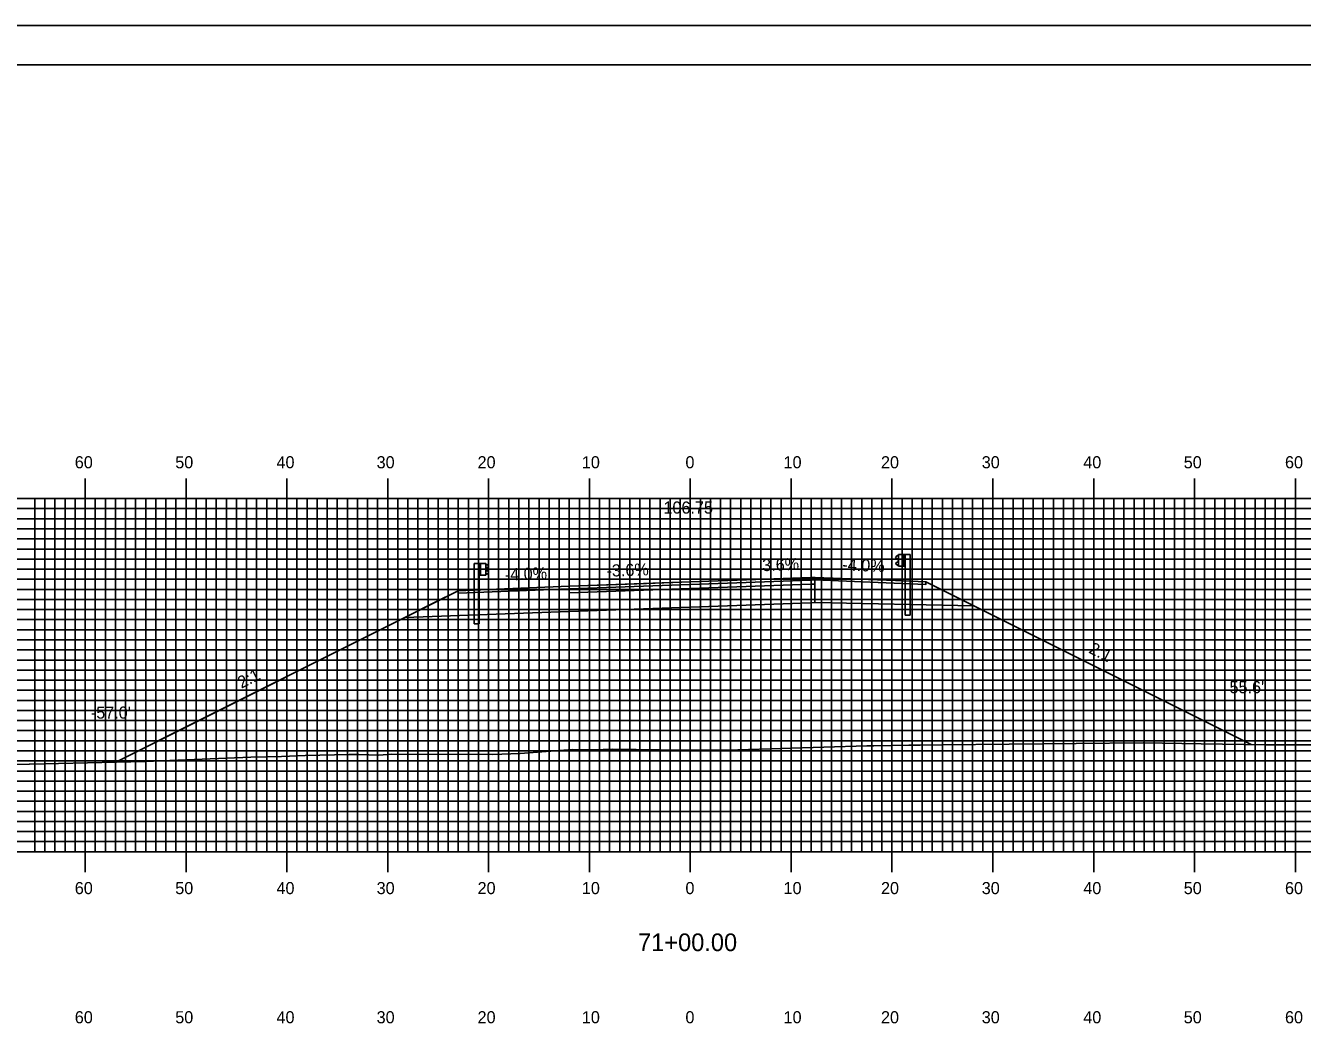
# Model space of a CAD drawing. Extents: x 1760217 to 1760560, y 442591 to 442811.
# Drawn here: x 1760316.8 to 1760443.4, y 442711.2 to 442810.5 of the extents above; entities that cross this region are included whole.
import ezdxf

# ---------------------------------------------------------------- set-up
doc = ezdxf.new("R2010")
doc.units = 0
for name, color, linetype in [('ANNOTATION', 7, 'Continuous'), ('BORDER', 7, 'Continuous'), ('D_Guardrail_Beam_Lt', 7, 'Continuous'), ('D_Guardrail_Beam_Rt', 7, 'Continuous'), ('D_Roadway_Centerline', 7, 'Continuous'), ('D_Roadway_Centerline_Text', 7, 'Continuous'), ('D_Roadway_Edge_Shoulder', 7, 'Continuous'), ('D_Roadway_Edge_TW', 7, 'Continuous'), ('D_Roadway_Pavement', 7, 'Continuous'), ('D_Roadway_SlopeLines', 7, 'Continuous'), ('D_Roadway_SubGrade', 7, 'Continuous'), ('D_Text_Standard', 7, 'Continuous'), ('H_V ANNOTATION', 7, 'Continuous'), ('MAJOR', 7, 'Continuous'), ('MINOR', 7, 'Continuous'), ('PLOT BOUNDARY', 7, 'Continuous'), ('S_Roadway_Centerline', 7, 'Continuous')]:
    doc.layers.add(name, color=color, linetype=linetype)

msp = doc.modelspace()

# ---------------------------------------------------------------- linework, layer by layer
at = {"layer": 'BORDER'}
msp.add_lwpolyline([(1760233.1, 442596.67), (1760553.1, 442596.67), (1760553.1, 442806.67), (1760233.1, 442806.67)], close=True, dxfattribs=at)
at = {"layer": 'D_Guardrail_Beam_Lt'}
for p, q in [((1760361.27, 442757.25), (1760361.27, 442751.25)), ((1760361.74, 442757.25), (1760361.27, 442757.25)), ((1760362.43, 442757.25), (1760361.74, 442757.25)), ((1760361.74, 442757.25), (1760361.74, 442756.08)), ((1760361.8, 442757.25), (1760361.8, 442756.08)), ((1760361.91, 442757.25), (1760361.91, 442756.08)), ((1760362.43, 442756.08), (1760362.43, 442757.25)), ((1760362.43, 442757.16), (1760362.5, 442757.15)), ((1760362.43, 442756.7), (1760362.43, 442756.63)), ((1760362.5, 442756.18), (1760362.43, 442756.16)), ((1760362.66, 442756.9), (1760362.47, 442756.76)), ((1760362.47, 442756.56), (1760362.66, 442756.43)), ((1760362.52, 442757.14), (1760362.66, 442757.04)), ((1760362.66, 442756.28), (1760362.52, 442756.18)), ((1760361.74, 442756.08), (1760362.43, 442756.08)), ((1760361.76, 442751.25), (1760361.76, 442756.08)), ((1760361.76, 442751.25), (1760361.27, 442751.25))]:
    msp.add_line(p, q, dxfattribs=at)
for centre, major_axis, start_param, end_param in [((1760362.51, 442756.7), (-0.0789, 0), 5.323254, 6.283185), ((1760362.51, 442756.63), (-0.0789, 0), 6.283185, 7.243116), ((1760362.5, 442757.11), (0.0417, 0), 0.959931, 1.376053), ((1760362.5, 442756.22), (0.0417, 0), 4.907132, 5.323254), ((1760362.61, 442756.97), (0.0877, 0), 5.323254, 7.243116), ((1760362.61, 442756.36), (0.0877, 0), 5.323254, 7.243116)]:
    msp.add_ellipse(centre, major_axis=major_axis, ratio=0.995501, start_param=start_param, end_param=end_param, dxfattribs=at)
at = {"layer": 'D_Guardrail_Beam_Rt'}
for p, q in [((1760403.25, 442758.02), (1760403.1, 442757.92)), ((1760403.1, 442757.77), (1760403.3, 442757.64)), ((1760403.3, 442757.44), (1760403.1, 442757.3)), ((1760403.34, 442758.04), (1760403.26, 442758.02)), ((1760403.33, 442757.57), (1760403.33, 442757.5)), ((1760403.34, 442758.12), (1760404.02, 442758.12)), ((1760403.34, 442756.96), (1760403.34, 442758.12)), ((1760403.86, 442758.12), (1760403.86, 442756.96)), ((1760403.96, 442758.12), (1760403.96, 442756.96)), ((1760404.02, 442758.12), (1760404.49, 442758.12)), ((1760404.02, 442758.12), (1760404.02, 442756.96)), ((1760404.49, 442758.12), (1760404.49, 442752.12)), ((1760403.1, 442757.16), (1760403.25, 442757.06)), ((1760403.26, 442757.05), (1760403.34, 442757.04)), ((1760404.02, 442756.96), (1760403.34, 442756.96)), ((1760404, 442752.12), (1760404, 442756.96)), ((1760404, 442752.12), (1760404.49, 442752.12))]:
    msp.add_line(p, q, dxfattribs=at)
for centre, major_axis, start_param, end_param in [((1760403.15, 442757.85), (-0.0877, 0), 5.323254, 7.243116), ((1760403.27, 442757.98), (-0.0417, 0), 4.907132, 5.323254), ((1760403.25, 442757.57), (0.0789, 0), 0, 0.959931), ((1760403.25, 442757.5), (0.0789, 0), 5.323254, 6.283185), ((1760403.15, 442757.23), (-0.0877, 0), 5.323254, 7.243116), ((1760403.27, 442757.09), (-0.0417, 0), 0.959931, 1.376053)]:
    msp.add_ellipse(centre, major_axis=major_axis, ratio=0.995501, start_param=start_param, end_param=end_param, dxfattribs=at)
at = {"layer": 'D_Roadway_Centerline'}
msp.add_lwpolyline([(1760325.68, 442737.53), (1760333.64, 442741.51), (1760354.41, 442751.9), (1760354.41, 442751.9), (1760357.2, 442753.29), (1760359.7, 442754.54), (1760361.82, 442754.63), (1760362.7, 442754.66), (1760362.7, 442754.66), (1760370.7, 442754.98), (1760370.71, 442754.98), (1760378.37, 442755.26), (1760382.7, 442755.41), (1760389.19, 442755.65), (1760394.7, 442755.85), (1760394.97, 442755.86), (1760395.06, 442755.86), (1760396.87, 442755.79), (1760403.06, 442755.54), (1760403.06, 442755.54), (1760406.07, 442755.42), (1760410.81, 442753.04), (1760438.32, 442739.29), (1760438.33, 442739.29)], dxfattribs=at)
at = {"layer": 'D_Roadway_Edge_Shoulder'}
for points in [[(1760370.7, 442754.98), (1760362.7, 442754.66), (1760362.7, 442754.66), (1760359.7, 442754.54), (1760359.7, 442754.29), (1760370.7, 442754.73)], [(1760395.06, 442755.86), (1760403.06, 442755.54), (1760403.06, 442755.54), (1760406.07, 442755.42), (1760406.07, 442755.17), (1760395.06, 442755.61)]]:
    msp.add_lwpolyline(points, close=True, dxfattribs=at)
at = {"layer": 'D_Roadway_Edge_TW'}
for points in [[(1760370.7, 442754.73), (1760370.7, 442754.98), (1760382.7, 442755.41), (1760394.7, 442755.85), (1760394.7, 442755.6), (1760382.7, 442755.16)], [(1760394.7, 442755.85), (1760395.06, 442755.86), (1760395.06, 442755.61), (1760394.7, 442755.6)]]:
    msp.add_lwpolyline(points, close=True, dxfattribs=at)
at = {"layer": 'D_Roadway_Pavement'}
for points in [[(1760370.7, 442754.32), (1760370.7, 442754.73), (1760382.7, 442755.16), (1760394.7, 442755.6), (1760394.7, 442755.18), (1760382.7, 442754.75)], [(1760394.7, 442755.6), (1760395.06, 442755.61), (1760395.06, 442755.19), (1760394.7, 442755.18)]]:
    msp.add_lwpolyline(points, close=True, dxfattribs=at)
for points in [[(1760395.06, 442755.61), (1760395.06, 442755.19)], [(1760395.06, 442755.61), (1760395.06, 442755.19)], [(1760370.7, 442754.73), (1760370.7, 442754.32)]]:
    msp.add_lwpolyline(points, dxfattribs=at)
at = {"layer": 'D_Roadway_SlopeLines'}
for points in [[(1760406.07, 442755.42), (1760438.33, 442739.29)], [(1760359.7, 442754.54), (1760325.68, 442737.53)]]:
    msp.add_lwpolyline(points, dxfattribs=at)
at = {"layer": 'D_Roadway_SubGrade'}
for points in [[(1760370.7, 442752.48), (1760370.7, 442754.32), (1760382.7, 442754.75), (1760394.7, 442755.18), (1760394.7, 442753.35), (1760382.7, 442752.91)], [(1760394.7, 442755.18), (1760395.06, 442755.19), (1760395.06, 442753.36), (1760394.7, 442753.35)], [(1760395.06, 442755.19), (1760395.06, 442755.61), (1760406.07, 442755.17), (1760406.07, 442755.42), (1760410.81, 442753.04), (1760395.06, 442753.36)], [(1760370.7, 442754.32), (1760370.7, 442754.73), (1760359.7, 442754.29), (1760359.7, 442754.54), (1760354.41, 442751.9), (1760370.7, 442752.48)]]:
    msp.add_lwpolyline(points, close=True, dxfattribs=at)
at = {"layer": 'MAJOR'}
for p, q in [((1760322.7, 442765.67), (1760322.7, 442763.67)), ((1760332.7, 442765.67), (1760332.7, 442763.67)), ((1760342.7, 442765.67), (1760342.7, 442763.67)), ((1760352.7, 442765.67), (1760352.7, 442763.67)), ((1760362.7, 442765.67), (1760362.7, 442763.67)), ((1760372.7, 442765.67), (1760372.7, 442763.67)), ((1760382.7, 442765.67), (1760382.7, 442763.67)), ((1760392.7, 442765.67), (1760392.7, 442763.67)), ((1760402.7, 442765.67), (1760402.7, 442763.67)), ((1760412.7, 442765.67), (1760412.7, 442763.67)), ((1760422.7, 442765.67), (1760422.7, 442763.67)), ((1760432.7, 442765.67), (1760432.7, 442763.67)), ((1760442.7, 442765.67), (1760442.7, 442763.67)), ((1760242.7, 442763.67), (1760522.7, 442763.67)), ((1760242.7, 442763.67), (1760522.7, 442763.67)), ((1760322.7, 442728.67), (1760322.7, 442763.67)), ((1760332.7, 442728.67), (1760332.7, 442763.67)), ((1760342.7, 442728.67), (1760342.7, 442763.67)), ((1760352.7, 442728.67), (1760352.7, 442763.67)), ((1760362.7, 442728.67), (1760362.7, 442763.67)), ((1760372.7, 442728.67), (1760372.7, 442763.67)), ((1760382.7, 442728.67), (1760382.7, 442763.67)), ((1760392.7, 442728.67), (1760392.7, 442763.67)), ((1760402.7, 442728.67), (1760402.7, 442763.67)), ((1760412.7, 442728.67), (1760412.7, 442763.67)), ((1760422.7, 442728.67), (1760422.7, 442763.67)), ((1760432.7, 442728.67), (1760432.7, 442763.67)), ((1760442.7, 442728.67), (1760442.7, 442763.67)), ((1760242.7, 442758.67), (1760522.7, 442758.67)), ((1760242.7, 442753.67), (1760522.7, 442753.67)), ((1760242.7, 442748.67), (1760522.7, 442748.67)), ((1760242.7, 442743.67), (1760522.7, 442743.67)), ((1760242.7, 442738.67), (1760522.7, 442738.67)), ((1760242.7, 442733.67), (1760522.7, 442733.67)), ((1760242.7, 442728.67), (1760522.7, 442728.67)), ((1760242.7, 442728.67), (1760522.7, 442728.67)), ((1760322.7, 442726.66), (1760322.7, 442728.67)), ((1760332.7, 442726.66), (1760332.7, 442728.67)), ((1760342.7, 442726.66), (1760342.7, 442728.67)), ((1760352.7, 442726.66), (1760352.7, 442728.67)), ((1760362.7, 442726.66), (1760362.7, 442728.67)), ((1760372.7, 442726.66), (1760372.7, 442728.67)), ((1760382.7, 442726.66), (1760382.7, 442728.67)), ((1760392.7, 442726.66), (1760392.7, 442728.67)), ((1760402.7, 442726.66), (1760402.7, 442728.67)), ((1760412.7, 442726.66), (1760412.7, 442728.67)), ((1760422.7, 442726.66), (1760422.7, 442728.67)), ((1760432.7, 442726.66), (1760432.7, 442728.67)), ((1760442.7, 442726.66), (1760442.7, 442728.67))]:
    msp.add_line(p, q, dxfattribs=at)
at = {"layer": 'MINOR'}
for p, q in [((1760242.7, 442762.67), (1760522.7, 442762.67)), ((1760317.7, 442728.67), (1760317.7, 442763.67)), ((1760318.7, 442728.67), (1760318.7, 442763.67)), ((1760319.7, 442728.67), (1760319.7, 442763.67)), ((1760320.7, 442728.67), (1760320.7, 442763.67)), ((1760321.7, 442728.67), (1760321.7, 442763.67)), ((1760323.7, 442728.67), (1760323.7, 442763.67)), ((1760324.7, 442728.67), (1760324.7, 442763.67)), ((1760325.7, 442728.67), (1760325.7, 442763.67)), ((1760326.7, 442728.67), (1760326.7, 442763.67)), ((1760327.7, 442728.67), (1760327.7, 442763.67)), ((1760328.7, 442728.67), (1760328.7, 442763.67)), ((1760329.7, 442728.67), (1760329.7, 442763.67)), ((1760330.7, 442728.67), (1760330.7, 442763.67)), ((1760331.7, 442728.67), (1760331.7, 442763.67)), ((1760333.7, 442728.67), (1760333.7, 442763.67)), ((1760334.7, 442728.67), (1760334.7, 442763.67)), ((1760335.7, 442728.67), (1760335.7, 442763.67)), ((1760336.7, 442728.67), (1760336.7, 442763.67)), ((1760337.7, 442728.67), (1760337.7, 442763.67)), ((1760338.7, 442728.67), (1760338.7, 442763.67)), ((1760339.7, 442728.67), (1760339.7, 442763.67)), ((1760340.7, 442728.67), (1760340.7, 442763.67)), ((1760341.7, 442728.67), (1760341.7, 442763.67)), ((1760343.7, 442728.67), (1760343.7, 442763.67)), ((1760344.7, 442728.67), (1760344.7, 442763.67)), ((1760345.7, 442728.67), (1760345.7, 442763.67)), ((1760346.7, 442728.67), (1760346.7, 442763.67)), ((1760347.7, 442728.67), (1760347.7, 442763.67)), ((1760348.7, 442728.67), (1760348.7, 442763.67)), ((1760349.7, 442728.67), (1760349.7, 442763.67)), ((1760350.7, 442728.67), (1760350.7, 442763.67)), ((1760351.7, 442728.67), (1760351.7, 442763.67)), ((1760353.7, 442728.67), (1760353.7, 442763.67)), ((1760354.7, 442728.67), (1760354.7, 442763.67)), ((1760355.7, 442728.67), (1760355.7, 442763.67)), ((1760356.7, 442728.67), (1760356.7, 442763.67)), ((1760357.7, 442728.67), (1760357.7, 442763.67)), ((1760358.7, 442728.67), (1760358.7, 442763.67)), ((1760359.7, 442728.67), (1760359.7, 442763.67)), ((1760360.7, 442728.67), (1760360.7, 442763.67)), ((1760361.7, 442728.67), (1760361.7, 442763.67)), ((1760363.7, 442728.67), (1760363.7, 442763.67)), ((1760364.7, 442728.67), (1760364.7, 442763.67)), ((1760365.7, 442728.67), (1760365.7, 442763.67)), ((1760366.7, 442728.67), (1760366.7, 442763.67)), ((1760367.7, 442728.67), (1760367.7, 442763.67)), ((1760368.7, 442728.67), (1760368.7, 442763.67)), ((1760369.7, 442728.67), (1760369.7, 442763.67)), ((1760370.7, 442728.67), (1760370.7, 442763.67)), ((1760371.7, 442728.67), (1760371.7, 442763.67)), ((1760373.7, 442728.67), (1760373.7, 442763.67)), ((1760374.7, 442728.67), (1760374.7, 442763.67)), ((1760375.7, 442728.67), (1760375.7, 442763.67)), ((1760376.7, 442728.67), (1760376.7, 442763.67)), ((1760377.7, 442728.67), (1760377.7, 442763.67)), ((1760378.7, 442728.67), (1760378.7, 442763.67)), ((1760379.7, 442728.67), (1760379.7, 442763.67)), ((1760380.7, 442728.67), (1760380.7, 442763.67)), ((1760381.7, 442728.67), (1760381.7, 442763.67)), ((1760383.7, 442728.67), (1760383.7, 442763.67)), ((1760384.7, 442728.67), (1760384.7, 442763.67)), ((1760385.7, 442728.67), (1760385.7, 442763.67)), ((1760386.7, 442728.67), (1760386.7, 442763.67)), ((1760387.7, 442728.67), (1760387.7, 442763.67)), ((1760388.7, 442728.67), (1760388.7, 442763.67)), ((1760389.7, 442728.67), (1760389.7, 442763.67)), ((1760390.7, 442728.67), (1760390.7, 442763.67)), ((1760391.7, 442728.67), (1760391.7, 442763.67)), ((1760393.7, 442728.67), (1760393.7, 442763.67)), ((1760394.7, 442728.67), (1760394.7, 442763.67)), ((1760395.7, 442728.67), (1760395.7, 442763.67)), ((1760396.7, 442728.67), (1760396.7, 442763.67)), ((1760397.7, 442728.67), (1760397.7, 442763.67)), ((1760398.7, 442728.67), (1760398.7, 442763.67)), ((1760399.7, 442728.67), (1760399.7, 442763.67)), ((1760400.7, 442728.67), (1760400.7, 442763.67)), ((1760401.7, 442728.67), (1760401.7, 442763.67)), ((1760403.7, 442728.67), (1760403.7, 442763.67)), ((1760404.7, 442728.67), (1760404.7, 442763.67)), ((1760405.7, 442728.67), (1760405.7, 442763.67)), ((1760406.7, 442728.67), (1760406.7, 442763.67)), ((1760407.7, 442728.67), (1760407.7, 442763.67)), ((1760408.7, 442728.67), (1760408.7, 442763.67)), ((1760409.7, 442728.67), (1760409.7, 442763.67)), ((1760410.7, 442728.67), (1760410.7, 442763.67)), ((1760411.7, 442728.67), (1760411.7, 442763.67)), ((1760413.7, 442728.67), (1760413.7, 442763.67)), ((1760414.7, 442728.67), (1760414.7, 442763.67)), ((1760415.7, 442728.67), (1760415.7, 442763.67)), ((1760416.7, 442728.67), (1760416.7, 442763.67)), ((1760417.7, 442728.67), (1760417.7, 442763.67)), ((1760418.7, 442728.67), (1760418.7, 442763.67)), ((1760419.7, 442728.67), (1760419.7, 442763.67)), ((1760420.7, 442728.67), (1760420.7, 442763.67)), ((1760421.7, 442728.67), (1760421.7, 442763.67)), ((1760423.7, 442728.67), (1760423.7, 442763.67)), ((1760424.7, 442728.67), (1760424.7, 442763.67)), ((1760425.7, 442728.67), (1760425.7, 442763.67)), ((1760426.7, 442728.67), (1760426.7, 442763.67)), ((1760427.7, 442728.67), (1760427.7, 442763.67)), ((1760428.7, 442728.67), (1760428.7, 442763.67)), ((1760429.7, 442728.67), (1760429.7, 442763.67)), ((1760430.7, 442728.67), (1760430.7, 442763.67)), ((1760431.7, 442728.67), (1760431.7, 442763.67)), ((1760433.7, 442728.67), (1760433.7, 442763.67)), ((1760434.7, 442728.67), (1760434.7, 442763.67)), ((1760435.7, 442728.67), (1760435.7, 442763.67)), ((1760436.7, 442728.67), (1760436.7, 442763.67)), ((1760437.7, 442728.67), (1760437.7, 442763.67)), ((1760438.7, 442728.67), (1760438.7, 442763.67)), ((1760439.7, 442728.67), (1760439.7, 442763.67)), ((1760440.7, 442728.67), (1760440.7, 442763.67)), ((1760441.7, 442728.67), (1760441.7, 442763.67)), ((1760242.7, 442761.67), (1760522.7, 442761.67)), ((1760242.7, 442760.67), (1760522.7, 442760.67)), ((1760242.7, 442759.67), (1760522.7, 442759.67)), ((1760242.7, 442757.67), (1760522.7, 442757.67)), ((1760242.7, 442756.67), (1760522.7, 442756.67)), ((1760242.7, 442755.67), (1760522.7, 442755.67)), ((1760242.7, 442754.67), (1760522.7, 442754.67)), ((1760242.7, 442752.67), (1760522.7, 442752.67)), ((1760242.7, 442751.67), (1760522.7, 442751.67)), ((1760242.7, 442750.67), (1760522.7, 442750.67)), ((1760242.7, 442749.67), (1760522.7, 442749.67)), ((1760242.7, 442747.67), (1760522.7, 442747.67)), ((1760242.7, 442746.67), (1760522.7, 442746.67)), ((1760242.7, 442745.67), (1760522.7, 442745.67)), ((1760242.7, 442744.67), (1760522.7, 442744.67)), ((1760242.7, 442742.67), (1760522.7, 442742.67)), ((1760242.7, 442741.67), (1760522.7, 442741.67)), ((1760242.7, 442740.67), (1760522.7, 442740.67)), ((1760242.7, 442739.67), (1760522.7, 442739.67)), ((1760242.7, 442737.67), (1760522.7, 442737.67)), ((1760242.7, 442736.67), (1760522.7, 442736.67)), ((1760242.7, 442735.67), (1760522.7, 442735.67)), ((1760242.7, 442734.67), (1760522.7, 442734.67)), ((1760242.7, 442732.67), (1760522.7, 442732.67)), ((1760242.7, 442731.67), (1760522.7, 442731.67)), ((1760242.7, 442730.67), (1760522.7, 442730.67)), ((1760242.7, 442729.67), (1760522.7, 442729.67))]:
    msp.add_line(p, q, dxfattribs=at)
at = {"layer": 'PLOT BOUNDARY'}
msp.add_lwpolyline([(1760216.91, 442590.55), (1760556.91, 442590.55), (1760556.91, 442810.55), (1760216.91, 442810.55)], close=True, dxfattribs=at)
at = {"layer": 'S_Roadway_Centerline'}
msp.add_lwpolyline([(1760305.63, 442737.28), (1760317.14, 442737.34), (1760317.18, 442737.34), (1760328.69, 442737.6), (1760339.12, 442738.03), (1760342.16, 442738.12), (1760344.52, 442738.2), (1760348.89, 442738.31), (1760349.83, 442738.32), (1760351.82, 442738.23), (1760353.1, 442738.33), (1760363.09, 442738.32), (1760365.83, 442738.4), (1760371.03, 442738.79), (1760373.09, 442738.78), (1760375.03, 442738.83), (1760379.68, 442738.77), (1760384.26, 442738.73), (1760387.42, 442738.76), (1760400.19, 442739.16), (1760400.45, 442739.17), (1760400.52, 442739.17), (1760400.9, 442739.18), (1760404.36, 442739.24), (1760405.48, 442739.22), (1760407.67, 442739.27), (1760427.62, 442739.45), (1760433.36, 442739.36), (1760439.7, 442739.27), (1760448.3, 442739.28)], dxfattribs=at)

# ---------------------------------------------------------------- texts
at = {"layer": 'ANNOTATION'}
for s, rotation, p in [('3.6%', 2.0618, (1760389.85, 442756.47)), ('-4.0%', 357.7095, (1760397.76, 442756.55)), ('-4.0%', 2.2905, (1760364.33, 442755.53)), ('-3.6%', 2.0618, (1760374.41, 442755.92)), ('2:1', 333.4344, (1760422.13, 442748.42)), ('2:1', 26.5639, (1760338.19, 442744.82))]:
    msp.add_text(s, height=1.2, rotation=rotation, dxfattribs=at).set_placement(p)
at = {"layer": 'D_Roadway_Centerline'}
for s in ['C', 'L']:
    msp.add_text(s, height=0.0146, dxfattribs=at).set_placement((1760382.7, 442755.41))
at = {"layer": 'D_Roadway_Centerline_Text'}
msp.add_text('106.75', height=1.2, dxfattribs=at).set_placement((1760380.04, 442762.18))
at = {"layer": 'D_Text_Standard'}
for s, p in [("55.6'", (1760436.17, 442744.38)), ("-57.0'", (1760323.26, 442741.86))]:
    msp.add_text(s, height=1.2, dxfattribs=at).set_placement(p)
at = {"layer": 'H_V ANNOTATION'}
for s, height, p in [('60', 1.2, (1760321.67, 442766.67)), ('50', 1.2, (1760331.63, 442766.67)), ('40', 1.2, (1760341.67, 442766.67)), ('30', 1.2, (1760351.6, 442766.67)), ('20', 1.2, (1760361.61, 442766.67)), ('10', 1.2, (1760371.95, 442766.67)), ('0', 1.2, (1760382.22, 442766.67)), ('10', 1.2, (1760391.95, 442766.67)), ('20', 1.2, (1760401.61, 442766.67)), ('30', 1.2, (1760411.6, 442766.67)), ('40', 1.2, (1760421.67, 442766.67)), ('50', 1.2, (1760431.63, 442766.67)), ('60', 1.2, (1760441.67, 442766.67)), ('60', 1.2, (1760321.67, 442724.47)), ('50', 1.2, (1760331.63, 442724.47)), ('40', 1.2, (1760341.67, 442724.47)), ('30', 1.2, (1760351.6, 442724.47)), ('20', 1.2, (1760361.61, 442724.47)), ('10', 1.2, (1760371.95, 442724.47)), ('0', 1.2, (1760382.22, 442724.47)), ('10', 1.2, (1760391.95, 442724.47)), ('20', 1.2, (1760401.61, 442724.47)), ('30', 1.2, (1760411.6, 442724.47)), ('40', 1.2, (1760421.67, 442724.47)), ('50', 1.2, (1760431.63, 442724.47)), ('60', 1.2, (1760441.67, 442724.47)), ('71+00.00', 1.75, (1760377.52, 442718.82)), ('60', 1.2, (1760321.67, 442711.67)), ('50', 1.2, (1760331.63, 442711.67)), ('40', 1.2, (1760341.67, 442711.67)), ('30', 1.2, (1760351.6, 442711.67)), ('20', 1.2, (1760361.61, 442711.67)), ('10', 1.2, (1760371.95, 442711.67)), ('0', 1.2, (1760382.22, 442711.67)), ('10', 1.2, (1760391.95, 442711.67)), ('20', 1.2, (1760401.61, 442711.67)), ('30', 1.2, (1760411.6, 442711.67)), ('40', 1.2, (1760421.67, 442711.67)), ('50', 1.2, (1760431.63, 442711.67)), ('60', 1.2, (1760441.67, 442711.67))]:
    msp.add_text(s, height=height, dxfattribs=at).set_placement(p)

doc.saveas('drawing.dxf')
